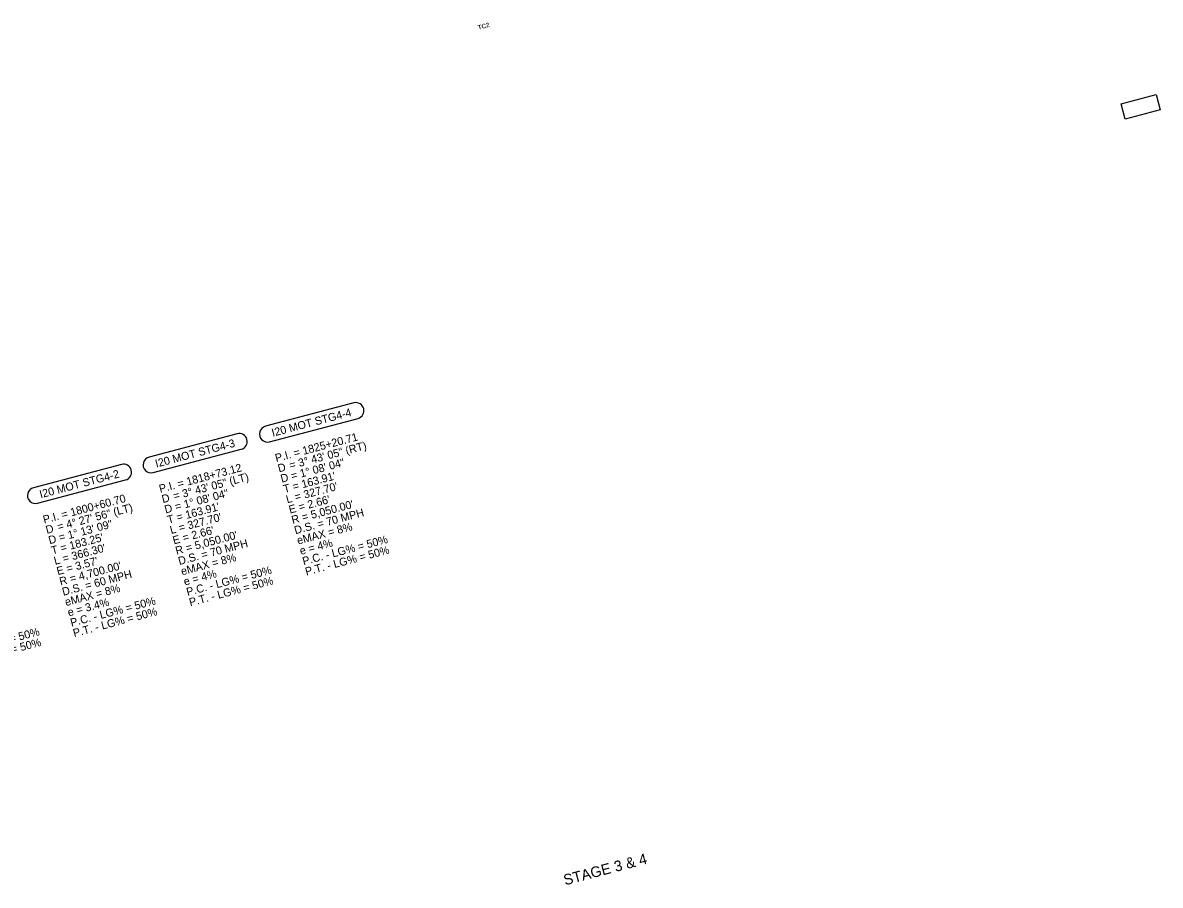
# Model space of a CAD drawing. Extents: x 2108880 to 2119953, y 864865 to 870169.
# Drawn here: x 2115689 to 2119953, y 866937 to 870169 of the extents above; entities that cross this region are included whole.
import ezdxf

# ---------------------------------------------------------------- set-up
doc = ezdxf.new("R2010")
doc.units = 0
for name, color, linetype in [('BR_BORDER LINES', 7, 'Continuous'), ('BR_CENTER LINES', 7, 'Continuous'), ('BR_GRID LINES', 7, 'Continuous'), ('BR_TEXT', 7, 'Continuous')]:
    doc.layers.add(name, color=color, linetype=linetype)

msp = doc.modelspace()

# ---------------------------------------------------------------- linework, layer by layer
at = {"layer": 'BR_CENTER LINES'}
for p, q in [((2116930.6, 868744.6), (2116599.2, 868656.8)), ((2116614.5, 868598.8), (2116945.9, 868686.6)), ((2116493, 868628.6), (2116162.7, 868541.1)), ((2116178, 868483.1), (2116508.3, 868570.6)), ((2116059.4, 868513.7), (2115729.1, 868426.2)), ((2115744.5, 868368.2), (2116074.8, 868455.7))]:
    msp.add_line(p, q, dxfattribs=at)
for centre, start, end in [((2116938.3, 868715.6), 284.8448, 104.8448), ((2116500.6, 868599.6), 284.8448, 104.8448), ((2116606.9, 868627.8), 104.8448, 284.8448), ((2116067.1, 868484.7), 284.8448, 104.8448), ((2116170.3, 868512.1), 104.8448, 284.8448), ((2115736.8, 868397.2), 104.8448, 284.8448)]:
    msp.add_arc(centre, 30, start, end, dxfattribs=at)
at = {"layer": 'BR_GRID LINES'}
for p, q in [((2119806.5, 869865.1), (2119937.5, 869899.9)), ((2119821.6, 869808.3), (2119806.5, 869865.1)), ((2119937.5, 869899.9), (2119952.6, 869843)), ((2119952.6, 869843), (2119821.6, 869808.3))]:
    msp.add_line(p, q, dxfattribs=at)

# ---------------------------------------------------------------- texts
at = {"layer": 'BR_BORDER LINES'}
for s, height, p in [('TC2', 16.67, (2117398.1, 870143.2)), ('STAGE 3 & 4', 40, (2117722.1, 866936))]:
    msp.add_text(s, height=height, rotation=14.8448, dxfattribs=at).set_placement(p)
at = {"layer": 'BR_CENTER LINES'}
for s, p in [('I20 MOT STG4-4', (2116626.5, 868617.4)), ('P.I. = 1825+20.71', (2116639.5, 868522.6)), ('I20 MOT STG4-3', (2116190, 868501.8)), ('    = 3%%d 43\' 05" (RT)', (2116649.8, 868484)), ('P.I. = 1818+73.12', (2116204.6, 868407.3)), ('D', (2116649.8, 868484)), ('D = 1%%d 08\' 04"', (2116660, 868445.3)), ('I20 MOT STG4-2', (2115756.4, 868386.8)), ('    = 3%%d 43\' 05" (LT)', (2116214.8, 868368.7)), ("T = 163.91'", (2116670.3, 868406.6)), ('D = 1%%d 08\' 04"', (2116225, 868330)), ("L = 327.70'", (2116680.5, 868368)), ('P.I. = 1800+60.70', (2115769.6, 868292)), ('D', (2116214.8, 868368.7)), ("E = 2.66'", (2116690.8, 868329.3)), ("R = 5,050.00'", (2116701, 868290.6)), ('    = 4%%d 27\' 56" (LT)', (2115779.8, 868253.4)), ("T = 163.91'", (2116235.3, 868291.3)), ("L = 327.70'", (2116245.5, 868252.7)), ('D.S. = 70 MPH', (2116711.3, 868252)), ('D = 1%%d 13\' 09"', (2115790.1, 868214.7)), ('eMAX = 8%', (2116721.5, 868213.3)), ('D', (2115779.8, 868253.4)), ("T = 183.25'", (2115800.3, 868176.1)), ("E = 2.66'", (2116255.8, 868214)), ("R = 5,050.00'", (2116266, 868175.3)), ('P.C. - LG% = 50%', (2116742, 868136)), ("L = 366.30'", (2115810.6, 868137.4)), ('D.S. = 70 MPH', (2116276.3, 868136.7)), ('e = 4%', (2116731.8, 868174.6)), ('P.T. - LG% = 50%', (2116752.3, 868097.3)), ("E = 3.57'", (2115820.8, 868098.7)), ('eMAX = 8%', (2116286.5, 868098)), ("R = 4,700.00'", (2115831.1, 868060.1)), ('D.S. = 60 MPH', (2115841.3, 868021.4)), ('e = 4%', (2116296.8, 868059.4)), ('P.C. - LG% = 50%', (2116307, 868020.7)), ('P.T. - LG% = 50%', (2116317.3, 867982)), ('eMAX = 8%', (2115851.6, 867982.7)), ('e = 3.4%', (2115861.8, 867944.1)), ('P.C. - LG% = 50%', (2115872.1, 867905.4)), ('P.T. - LG% = 50%', (2115882.3, 867866.7)), ('P.C. - LG% = 50%', (2115437.1, 867790.1)), ('P.T. - LG% = 50%', (2115447.3, 867751.4))]:
    msp.add_text(s, height=30, rotation=14.8448, dxfattribs=at).set_placement(p)
at = {"layer": 'BR_TEXT'}
msp.add_text('TC2', height=16.67, rotation=14.8448, dxfattribs=at).set_placement((2117397.3, 870143))

doc.saveas('drawing.dxf')
